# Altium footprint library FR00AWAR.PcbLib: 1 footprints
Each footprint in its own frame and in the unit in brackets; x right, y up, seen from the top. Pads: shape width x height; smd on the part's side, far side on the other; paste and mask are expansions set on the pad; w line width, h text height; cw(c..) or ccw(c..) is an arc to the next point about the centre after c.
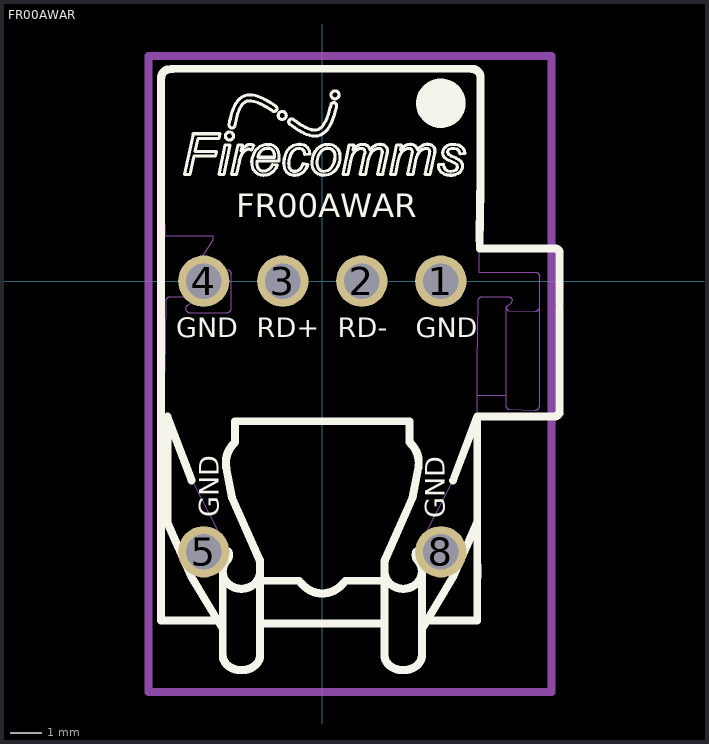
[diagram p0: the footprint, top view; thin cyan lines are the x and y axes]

## FR00AWAR [mil] "RedLink® Analogue Receiver Tilted Package"
height 600
pads (6):
  round 65 hole 45: 1(150,0) 2(50,0) 3(-50,0) 4(-150,0) 5(-150,-342.52) 8(150,-342.52)
Top Overlay:
  drawing of 2404 lines, arcs and shapes, not listed
  text "GND" at -185.04,-70.87 h25
  text "RD+" at -82.68,-70.87 h25
  text "RD-" at 19.68,-70.87 h25
  text "GND" at 118.11,-70.87 h25
  text "GND" at 155,-300 h25
  text "GND" at -131,-299 h25
  text "FR00AWAR" at -109,81 h30
Mechanical 2:
  lines w10: -220,-520 290,-520 290,285 -220,285 -220,-520
Mechanical 19:
  drawing of 2824 lines, arcs and shapes, not listed
3D body "Tiltet.stp": height 633.84, standoff -337.66, extent -205,-721.77 273.74,268.47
